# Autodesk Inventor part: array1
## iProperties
Author: Administrator
Created: 2000-12
Part Number: array1
Document SubType Name: Modeling
Designer: Administrator
Control State: 0
Master: False
Checked Out: False
PropertySet Name: Design Tracking Control
Shininess: 0.0
PropertySet Name: _Private Model Information
Density: 0.0
Volumn: 0.0
Area: 0.0
PropertySet Name: Model Information
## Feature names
1. Revolution1
2. Extrusion1
3. Circular Pattern1
